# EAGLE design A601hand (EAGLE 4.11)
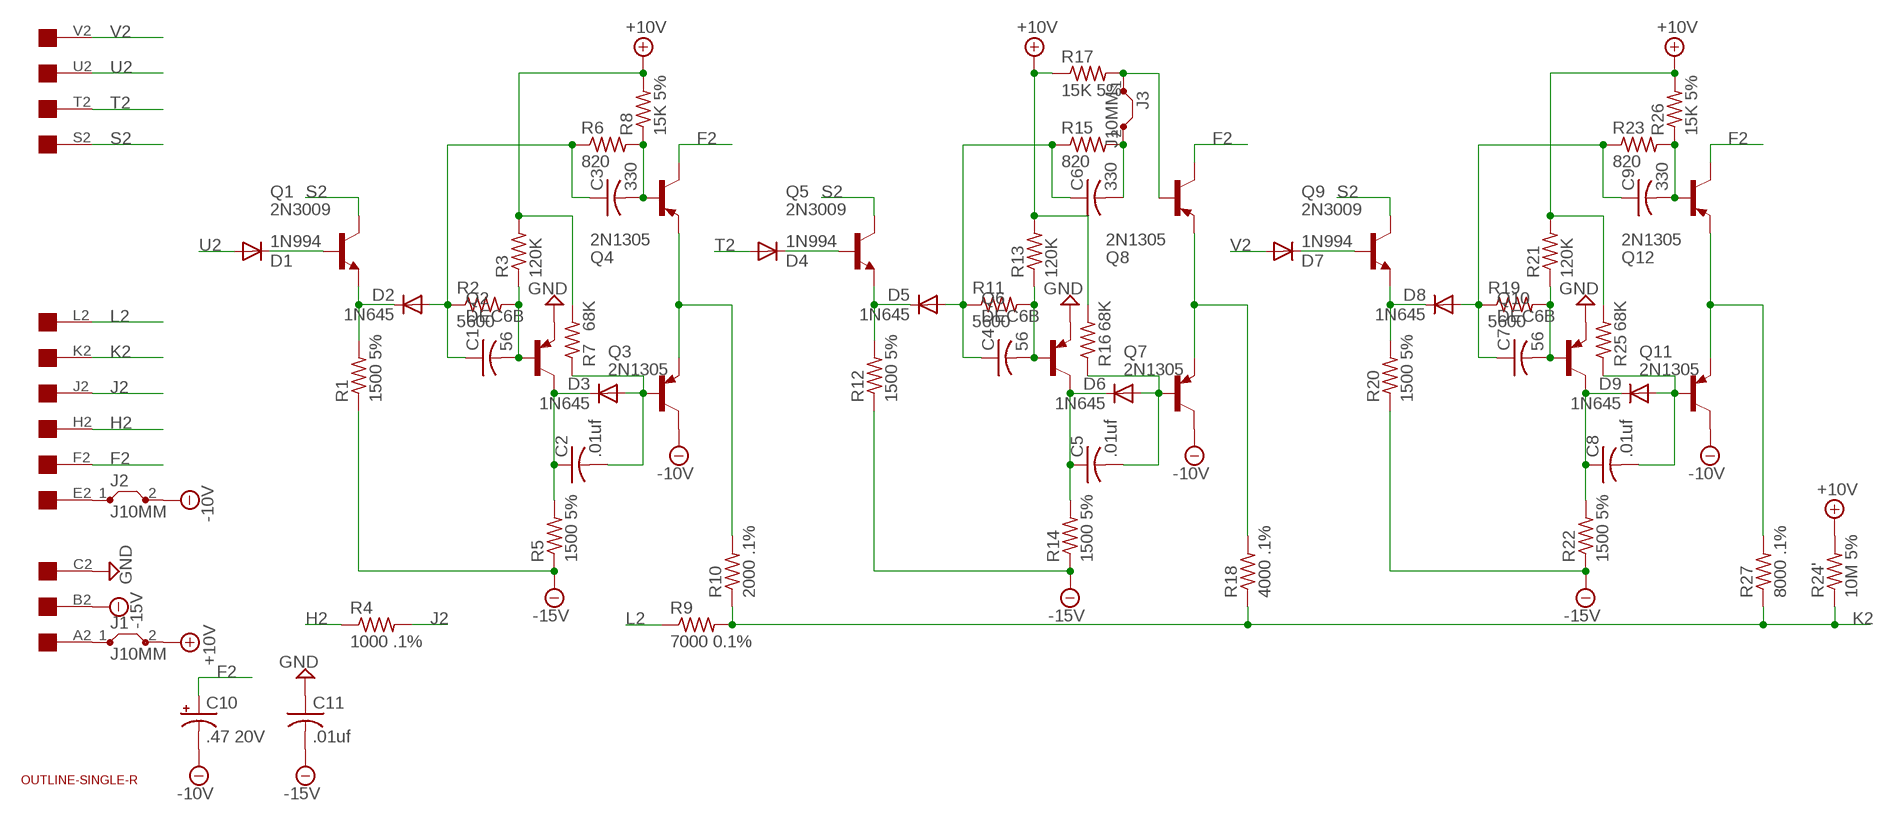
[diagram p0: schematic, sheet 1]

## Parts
C1  56  C-US075-032X103  [C075-032X103]
C2  .01uf  C-US050-025X075  [C050-025X075]
C3  330  C-US102-043X133  [C102-043X133]
C4  56  C-US075-032X103  [C075-032X103]
C5  .01uf  C-US050-025X075  [C050-025X075]
C6  330  C-US102-043X133  [C102-043X133]
C7  56  C-US075-032X103  [C075-032X103]
C8  .01uf  C-US050-025X075  [C050-025X075]
C9  330  C-US102-043X133  [C102-043X133]
C10  .47 20V  CPOL-USE22-6AXIAL  [E22-6]
C11  .01uf  C-US050-025X075  [C050-025X075]
D1  1N994  1N4148  [DO35-10]
D2  1N645  1N4148  [DO35-10]
D3  1N645  1N4148  [DO35-10]
D4  1N994  1N4148  [DO35-10]
D5  1N645  1N4148  [DO35-10]
D6  1N645  1N4148  [DO35-10]
D7  1N994  1N4148  [DO35-10]
D8  1N645  1N4148  [DO35-10]
D9  1N645  1N4148  [DO35-10]
J1  J10MM  [10]
J2  J10MM  [10]
J3  J10MM  [10]
Q1  2N3009  2N1613-NPN-TO39-EBC  [TO39]
Q2  DEC6B  2N2904A  [TO39]
Q3  2N1305  2N2904A  [TO39]
Q4  2N1305  2N2904A  [TO39]
Q5  2N3009  2N1613-NPN-TO39-EBC  [TO39]
Q6  DEC6B  2N2904A  [TO39]
Q7  2N1305  2N2904A  [TO39]
Q8  2N1305  2N2904A  [TO39]
Q9  2N3009  2N1613-NPN-TO39-EBC  [TO39]
Q10  DEC6B  2N2904A  [TO39]
Q11  2N1305  2N2904A  [TO39]
Q12  2N1305  2N2904A  [TO39]
R1  1500 5%  R-US_0207/10  [0207/10]
R2  5600  R-US_0207/10  [0207/10]
R3  120K  R-US_0207/10  [0207/10]
R4  1000 .1%  R-US_0309/12  [0309/12]
R5  1500 5%  R-US_0207/10  [0207/10]
R6  820  R-US_0207/10  [0207/10]
R7  68K  R-US_0207/10  [0207/10]
R8  15K 5%  R-US_0207/10  [0207/10]
R9  7000 0.1%  R-US_0309/12  [0309/12]
R10  2000 .1%  R-US_0309/12  [0309/12]
R11  5600  R-US_0207/10  [0207/10]
R12  1500 5%  R-US_0207/10  [0207/10]
R13  120K  R-US_0207/10  [0207/10]
R14  1500 5%  R-US_0207/10  [0207/10]
R15  820  R-US_0207/10  [0207/10]
R16  68K  R-US_0207/10  [0207/10]
R17  15K 5%  R-US_0207/10  [0207/10]
R18  4000 .1%  R-US_0309/12  [0309/12]
R19  5600  R-US_0207/10  [0207/10]
R20  1500 5%  R-US_0207/10  [0207/10]
R21  120K  R-US_0207/10  [0207/10]
R22  1500 5%  R-US_0207/10  [0207/10]
R23  820  R-US_0207/10  [0207/10]
R24'  10M 5%  R-US_0207/10  [0207/10]
R25  68K  R-US_0207/10  [0207/10]
R26  15K 5%  R-US_0207/10  [0207/10]
R27  8000 .1%  R-US_0309/12  [0309/12]
U$2  OUTLINE-SINGLE-R  [SINGLE-R]
U$3  EDGE-1  [EDGE-CON1]

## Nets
+10V: J1.2 R3.2 R7.2 R8.2 R13.2 R16.2 R17.1 R21.2 R24'.2 R25.2 R26.2
-10V: C10.- J2.2 Q3.3(C) Q7.3(C) Q11.3(C)
-15V: C11.2 R1.1 R5.1 R12.1 R14.1 R20.1 R22.1 U$3.B2
F2: C10.+ Q4.3(C) Q8.3(C) Q12.3(C) U$3.F2
GND [supply]: C11.1 Q2.1(E) Q6.1(E) Q10.1(E) U$3.C2
H2: R4.1 U$3.H2
J2: R4.2 U$3.J2
K2: R9.2 R10.1 R18.1 R24'.1 R27.1 U$3.K2
L2: R9.1 U$3.L2
N$1: D1.C Q1.2(B)
N$2: D2.C Q1.1(E) R1.2
N$3: C1.1 C3.1 D2.A R2.1 R6.1
N$4: C1.2 Q2.2(B) R2.2 R3.1
N$5: C3.2 Q4.2(B) R6.2 R8.1
N$6: C2.1 D3.C Q2.3(C) R5.2
N$7: C2.2 D3.A Q3.2(B) R7.1
N$8: Q3.1(E) Q4.1(E) R10.2
N$9: J2.1 U$3.E2
N$10: D4.C Q5.2(B)
N$11: D5.C Q5.1(E) R12.2
N$12: C4.1 C6.1 D5.A R11.1 R15.1
N$13: C4.2 Q6.2(B) R11.2 R13.1
N$14: C6.2 J3.2 R15.2
N$15: C5.1 D6.C Q6.3(C) R14.2
N$16: C5.2 D6.A Q7.2(B) R16.1
N$17: Q7.1(E) Q8.1(E) R18.2
N$18: D7.C Q9.2(B)
N$19: D8.C Q9.1(E) R20.2
N$20: C7.1 C9.1 D8.A R19.1 R23.1
N$21: C7.2 Q10.2(B) R19.2 R21.1
N$22: C9.2 Q12.2(B) R23.2 R26.1
N$23: C8.1 D9.C Q10.3(C) R22.2
N$24: C8.2 D9.A Q11.2(B) R25.1
N$25: Q11.1(E) Q12.1(E) R27.2
N$26: J1.1 U$3.A2
N$27: J3.1 Q8.2(B) R17.2
S2: Q1.3(C) Q5.3(C) Q9.3(C) U$3.S2
T2: D4.A U$3.T2
U2: D1.A U$3.U2
V2: D7.A U$3.V2
Unconnected: U$3.D2 U$3.M2 U$3.N2 U$3.P2 U$3.R2

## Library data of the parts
C1-C9 C11 = rcl:C-US: CAPACITOR, American symbol
C10 = rcl:CPOL-US: POLARIZED CAPACITOR, American symbol
D1-D9 = diode:1N4148: DIODE
J1-J3 = jumper:J: Bridge
Q1 Q5 Q9 = transistor:*-NPN-: NPN Transistror
Q2-Q4 Q6-Q8 Q10-Q12 = transistor-pnp:2N2904*: PNP Transistror
R1-R23 R24' R25-R27 = rcl:R-US_: RESISTOR, American symbol
U$2 = dec-con:OUTLINE-*: Board outlines for DEC boards.
U$3 = dec-con:EDGE-1: Single-Sided DEC Edge Connector -- (side 2)

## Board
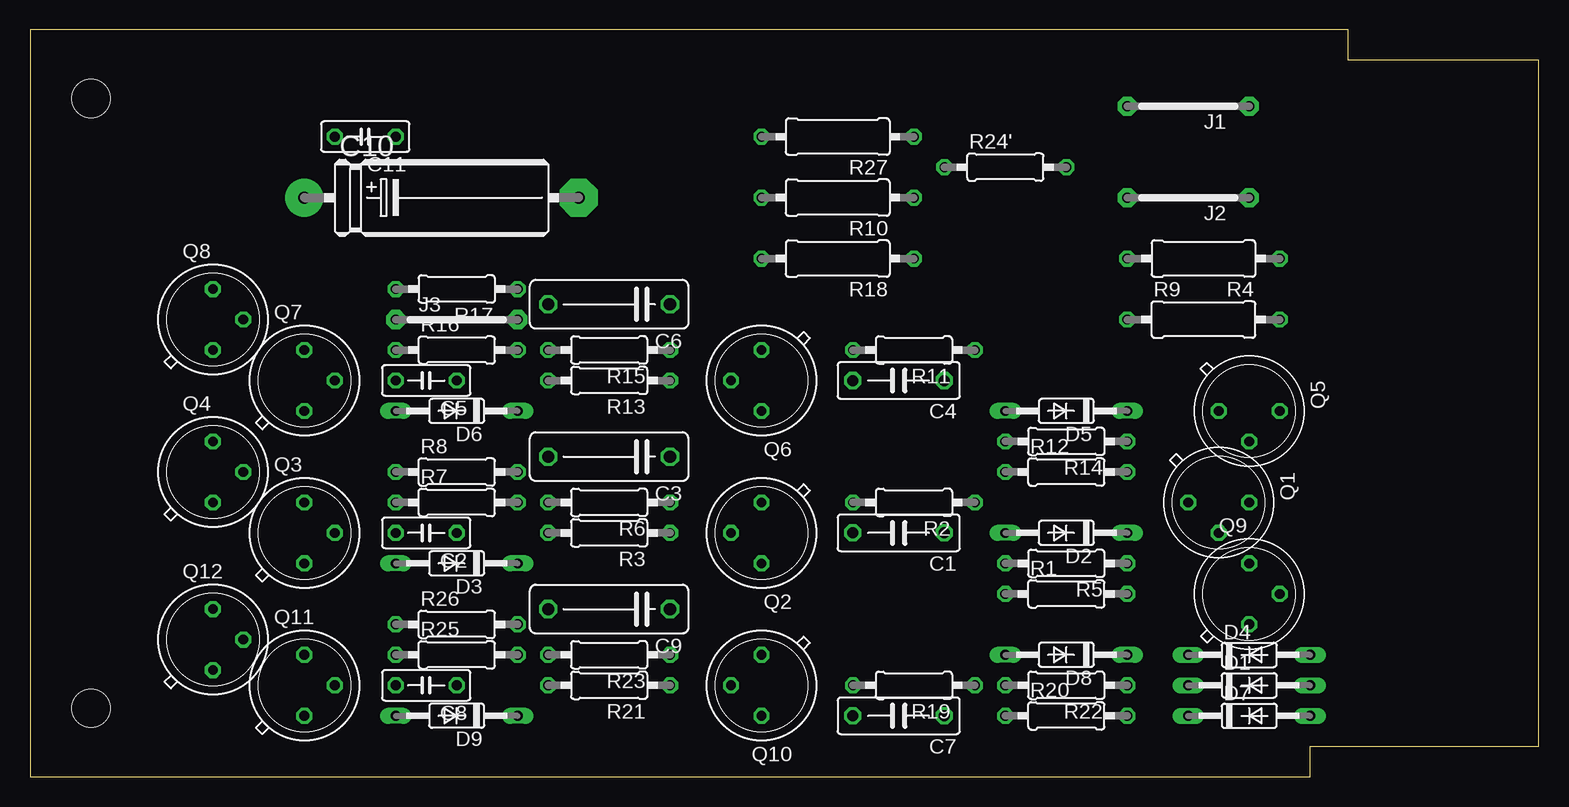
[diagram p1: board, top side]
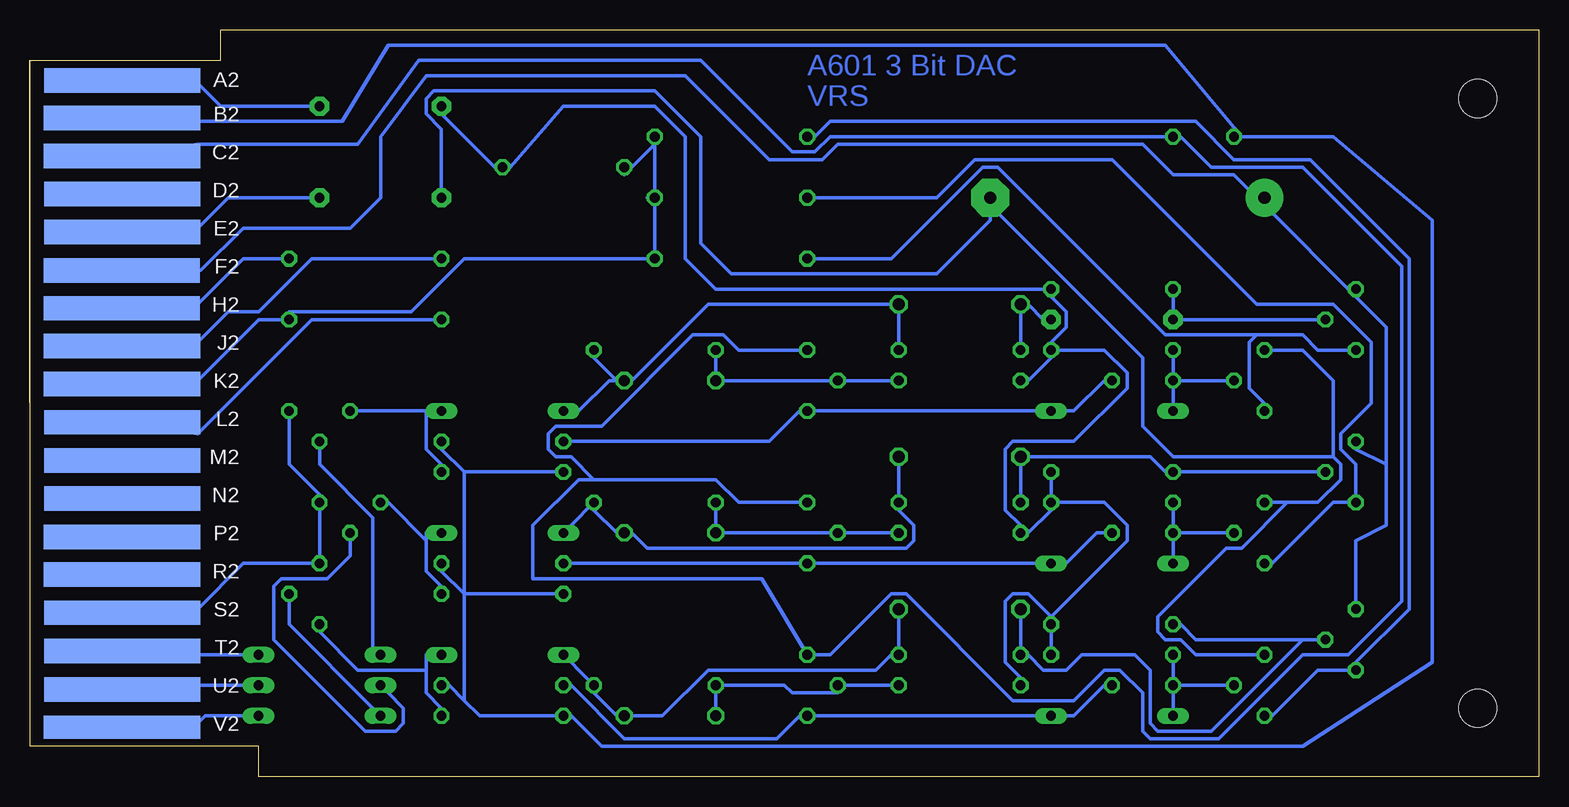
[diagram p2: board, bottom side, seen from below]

Size 125.73 x 62.23 mm. Coordinates in mm from the lower left corner, seen from the top.
Copper layers (1*16): Top 0.035mm / dielectric 1.5mm / Bottom 0.035mm
Design rules "15mils": minimum track width 12mil, minimum drill 24mil, track to track 12mil, track to pad 10mil, pad to pad 10mil, via to via 10mil, smd to smd 10mil, copper to edge 25mil, drill to drill 10mil, minimum pad ring 10mil, minimum via ring 8mil, stop-mask expansion 0mil, vias tented up to drill 0mil, thermal gap 10mil

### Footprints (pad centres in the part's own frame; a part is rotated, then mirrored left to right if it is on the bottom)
C075-032X103 = drill 0.914 octagon: 1 -3.81,0; 2 3.81,0
C050-025X075 = drill 0.813 octagon: 1 -2.54,0; 2 2.54,0
C102-043X133 = drill 1.016 octagon: 1 -5.08,0; 2 5.08,0
E22-6 = drill 1.016 pad 3.15 round: + -11.43,0 | drill 1.016 pad 3.15 octagon: - 11.43,0
DO35-10 = drill 0.813 long: A 5.08,0; C -5.08,0
10 = drill 0.813 pad 1.6 octagon: 1 -5.08,0; 2 5.08,0
TO39 = drill 0.813 octagon: 1 0,-2.54; 2 2.54,0; 3 0,2.54
0207/10 = drill 0.813 octagon: 1 -5.08,0; 2 5.08,0
0309/12 = drill 0.813 octagon: 1 -6.35,0; 2 6.35,0
SINGLE-R = hole 3.175: 5.08,5.715; 5.08,56.515
EDGE-CON1 = smd 13.017 x 2.032 bottom: A2 7.69,4.194; B2 7.668,7.328; C2 7.668,10.49; D2 7.693,13.665; E2 7.693,16.84; F2 7.642,20.041; H2 7.642,23.19; J2 7.668,26.34; K2 7.668,29.515; L2 7.693,32.69; M2 7.693,35.89; N2 7.693,39.04; P2 7.668,42.24; R2 7.668,45.39; S2 7.693,48.565; T2 7.693,51.74; U2 7.693,54.966 | smd 13.017 x 1.905 bottom: V2 7.668,58.102

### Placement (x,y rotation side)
C1  72.39,20.32 180 top
C2  33.02,20.32 180 top
C3  48.26,26.67 180 top
C4  72.39,33.02 180 top
C5  33.02,33.02 180 top
C6  48.26,39.37 180 top
C7  72.39,5.08 180 top
C8  33.02,7.62 180 top
C9  48.26,13.97 180 top
C10  34.29,48.26 0 top
C11  27.94,53.34 180 top
D1  101.6,7.62 0 top
D2  86.36,20.32 180 top
D3  35.56,17.78 180 top
D4  101.6,10.16 0 top
D5  86.36,30.48 180 top
D6  35.56,30.48 180 top
D7  101.6,5.08 0 top
D8  86.36,10.16 180 top
D9  35.56,5.08 180 top
J1  96.52,55.88 180 top
J2  96.52,48.26 180 top
J3  35.56,38.1 0 top
Q1  99.06,22.86 270 top
Q2  60.96,20.32 180 top
Q3  22.86,20.32 0 top
Q4  15.24,25.4 0 top
Q5  101.6,30.48 270 top
Q6  60.96,33.02 180 top
Q7  22.86,33.02 0 top
Q8  15.24,38.1 0 top
Q9  101.6,15.24 0 top
Q10  60.96,7.62 180 top
Q11  22.86,7.62 0 top
Q12  15.24,11.43 0 top
R1  86.36,15.24 0 top
R2  73.66,22.86 180 top
R3  48.26,20.32 180 top
R4  97.79,43.18 180 top
R5  86.36,17.78 180 top
R6  48.26,22.86 180 top
R7  35.56,22.86 0 top
R8  35.56,25.4 0 top
R9  97.79,38.1 0 top
R10  67.31,48.26 180 top
R11  73.66,35.56 180 top
R12  86.36,25.4 0 top
R13  48.26,33.02 180 top
R14  86.36,27.94 180 top
R15  48.26,35.56 180 top
R16  35.56,35.56 0 top
R17  35.56,40.64 180 top
R18  67.31,43.18 180 top
R19  73.66,7.62 180 top
R20  86.36,5.08 0 top
R21  48.26,7.62 180 top
R22  86.36,7.62 180 top
R23  48.26,10.16 180 top
R24'  81.28,50.8 0 top
R25  35.56,10.16 0 top
R26  35.56,12.7 0 top
R27  67.31,53.34 180 top
U$2  0,0 0 top
U$3  125.73,62.23 180 top

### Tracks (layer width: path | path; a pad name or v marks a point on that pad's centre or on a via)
+10V
  Bottom 0.305: R25.2 40.64,10.79 40.64,12.06 R26.2 | 40.64,13.34 42.55,15.24 43.81,15.24 44.45,14.61 44.45,9.53 43.18,8.26 R21.2 | R26.2 40.64,13.34 | R7.2 40.64,23.5 40.64,24.77 R8.2 | R7.2 40.64,22.23 42.55,20.32 R3.2 43.18,20.95 44.45,22.23 44.45,27.3 43.81,27.94 38.73,27.94 34.29,32.38 34.29,33.66 36.2,35.56 40.01,35.56 R16.2 | R13.2 42.55,33.02 40.64,34.92 R16.2 | R16.2 40.64,36.2 39.37,37.47 39.37,38.73 40.64,40.01 R17.1 41.27,40.64 55.24,40.64 55.88,40.64 68.58,40.64 71.12,43.18 71.12,53.34 73.66,55.88 81.28,55.88 85.72,50.8 R24'.2 87,50.8 91.44,55.24 J1.2 | 40.64,13.34 34.29,19.68 34.29,20.95 36.2,22.86 40.01,22.86 R7.2 | R26.2 40.64,13.34
-10V
  Bottom 0.305: 17.14,26.67 30.48,26.67 33.02,29.21 33.02,34.92 45.09,46.99 C10.- 45.72,46.35 50.16,41.91 67.31,41.91 69.85,44.45 69.85,53.34 73.66,57.15 92.08,57.15 92.71,56.52 92.71,55.24 91.44,53.98 91.44,48.9 J2.2 | 17.14,26.67 16.51,26.04 16.51,24.77 18.41,22.86 20.95,22.86 | 20.95,22.86 22.23,22.86 Q3.3 | 20.95,22.86 24.77,19.05 26.04,19.05 31.75,13.34 31.75,12.06 31.11,11.43 29.84,11.43 28.57,10.16 23.5,10.16 Q11.3 | 17.14,26.67 17.14,33.02 19.68,35.56 Q7.3
-15V
  Bottom 0.305: R1.1 81.92,15.24 89.53,15.24 | 89.53,6.35 90.81,7.62 R22.1 | 89.53,6.35 88.27,5.08 81.92,5.08 R20.1 80.64,5.08 78.11,2.54 19.68,2.54 8.89,9.53 8.89,46.35 17.14,53.34 24.77,53.34 | 89.53,15.24 91.44,17.14 R5.1 | 89.53,6.35 89.53,15.24 | 89.53,25.4 91.44,27.3 R14.1 | 89.53,15.24 89.53,25.4 | 24.77,53.34 C11.2 | 24.77,53.34 31.11,60.96 95.89,60.96 99.69,54.61 111.76,54.61 U$3.B2 | 24.77,53.34 C11.2 | 89.53,25.4 81.92,25.4 R12.1 | 24.77,53.34 C11.2
F2
  Bottom 0.305: 12.7,26.04 12.7,20.95 15.24,19.68 15.24,14.61 Q12.3 | 12.7,26.04 15.24,27.3 Q4.3 | 12.7,26.04 12.7,37.47 15.24,40.01 Q8.3 15.88,40.64 22.23,46.99 C10.+ | U$3.F2 111.48,42.19 107.95,45.72 104.14,45.72 99.06,45.72 96.52,48.26 96.52,53.34 92.71,58.42 71.12,58.42 64.14,51.44 59.69,51.44 58.42,52.7 33.02,52.7 30.48,50.16 25.4,50.16 24.13,48.9 | C10.+ 24.13,48.9 | C10.+ 24.13,48.9
GND
  Bottom 0.305: U$3.C2 111.76,52.7 98.42,52.7 93.34,59.69 69.85,59.69 62.23,52.07 60.33,52.07 59.05,53.34 52.7,53.34 31.11,53.34 C11.1 29.84,53.34 27.3,50.8 19.68,50.8 11.43,42.55 11.43,14.61 15.88,10.16 19.68,10.16 26.67,3.17 32.38,3.17 33.02,3.81 33.02,6.99 34.92,8.89 36.2,8.89 38.73,6.35 43.81,6.35 52.7,15.24 53.98,15.24 59.05,10.16 60.33,10.16 Q10.1 64.77,16.51 83.82,16.51 83.82,20.95 80.01,24.77 78.74,24.77 | 78.74,24.77 68.58,24.77 66.67,22.86 61.59,22.86 Q2.1 | 78.74,24.77 80.64,26.67 81.92,26.67 82.55,27.3 82.55,28.57 81.92,29.21 78.11,29.21 70.48,36.83 67.94,36.83 66.67,35.56 61.59,35.56 Q6.1
H2
  Bottom 0.305: R4.1 104.78,43.18 107.95,43.18 111.76,39.37 U$3.H2
J2
  Bottom 0.305: R4.2 92.08,43.18 102.23,43.18 106.68,38.73 109.22,38.73 111.76,36.2 U$3.J2
K2
  Bottom 0.305: 73.66,43.81 73.66,47.62 R10.1 74.3,48.26 | 73.66,43.81 73.66,52.7 | 73.66,52.7 R27.1 73.66,52.7 | 76.2,50.16 R24'.1 75.56,50.8 73.66,52.7 | U$3.K2 111.76,33.02 106.68,38.1 104.78,38.1 R9.2 104.14,38.73 93.98,38.73 89.53,43.18 74.3,43.18 R18.1 73.66,43.81
L2
  Bottom 0.305: R9.1 92.08,38.1 102.23,38.1 111.76,28.57 U$3.L2
N$1
  Bottom 0.305: D1.C 95.89,6.99 94.61,5.71 94.61,4.45 95.25,3.81 97.79,3.81 105.41,11.43 105.41,15.88 104.78,16.51 100.97,16.51 99.06,18.41 99.06,19.68 Q1.2
N$2
  Bottom 0.305: 92.71,19.68 92.71,20.32 D2.C | 92.71,19.68 92.71,17.14 91.44,15.88 R1.2 | 92.71,19.68 95.89,22.86 Q1.1
N$3
  Bottom 0.305: C3.1 53.34,26.04 53.34,23.5 R6.1 53.34,22.23 52.07,20.95 52.07,19.68 52.7,19.05 74.3,19.05 75.56,20.32 C1.1 76.83,20.32 78.74,22.23 R2.1 80.64,20.95 D2.A
N$4
  Bottom 0.305: R2.2 68.58,22.23 68.58,20.95 C1.2 67.94,20.32 59.05,20.32 Q2.2 57.78,20.32 53.98,20.32 R3.1
N$5
  Bottom 0.305: R6.2 43.18,23.5 43.18,26.04 C3.2 42.55,26.67 32.38,26.67 31.11,25.4 R8.1 29.84,25.4 18.41,25.4 Q4.2
N$6
  Bottom 0.305: C2.1 36.2,20.32 36.83,20.32 39.37,17.78 D3.C 41.91,17.78 60.33,17.78 Q2.3 61.59,17.78 80.64,17.78 R5.2
N$7
  Bottom 0.305: Q3.2 26.04,20.32 29.84,20.32 C2.2 | D3.A 30.48,18.41 30.48,19.68 C2.2 | R7.1 30.48,22.23 30.48,20.95 C2.2
N$8
  Bottom 0.305: Q3.1 22.23,17.78 17.14,22.86 15.88,22.86 Q4.1 15.24,23.5 15.24,26.04 16.51,27.3 16.51,28.57 13.97,31.11 13.97,36.2 17.14,39.37 23.5,39.37 35.56,51.44 46.99,51.44 50.16,48.26 60.33,48.26 R10.2
N$9
  Bottom 0.305: J2.1 102.23,48.26 109.22,48.26 111.76,45.72 U$3.E2
N$10
  Bottom 0.305: D4.C 97.16,10.79 97.16,21.59 101.6,26.04 101.6,27.3 Q5.2
N$11
  Bottom 0.305: 92.71,30.48 92.71,27.3 91.44,26.04 R12.2 | 92.71,30.48 D5.C 92.71,30.48 | 92.71,30.48 98.42,30.48 Q5.1
N$12
  Bottom 0.305: R15.1 53.34,36.2 53.34,38.73 C6.1 53.98,39.37 69.22,39.37 75.56,33.02 C4.1 | 76.83,33.02 77.47,33.02 80.01,30.48 D5.A | C4.1 76.83,33.02 | 76.83,33.02 78.74,34.92 R11.1 | C4.1 76.83,33.02
N$13
  Bottom 0.305: R11.2 68.58,34.92 68.58,33.66 C4.2 67.94,33.02 59.05,33.02 Q6.2 57.78,33.02 53.98,33.02 R13.1
N$14
  Bottom 0.305: R15.2 43.18,36.2 43.18,38.73 C6.2 42.55,39.37 41.27,38.1 J3.2
N$15
  Bottom 0.305: C5.1 36.2,33.02 38.73,30.48 39.37,30.48 D6.C 41.91,30.48 60.33,30.48 Q6.3 61.59,30.48 64.14,27.94 80.64,27.94 R14.2
N$16
  Bottom 0.305: Q7.2 26.04,33.02 29.84,33.02 C5.2 | D6.A 30.48,31.11 30.48,32.38 C5.2 | R16.1 30.48,34.92 30.48,33.66 C5.2
N$17
  Bottom 0.305: 23.5,36.83 19.68,36.83 18.41,35.56 15.88,35.56 Q8.1 | 23.5,36.83 24.13,36.2 24.13,32.38 22.86,31.11 Q7.1 | 23.5,36.83 31.11,36.83 45.09,50.8 46.35,50.8 53.98,43.18 57.78,43.18 60.33,43.18 R18.2
N$18
  Bottom 0.305: D7.C 97.16,5.71 104.14,12.7 104.14,14.61 Q9.2
N$19
  Bottom 0.305: 92.71,8.89 92.71,10.16 D8.C | 92.71,8.89 92.71,6.99 91.44,5.71 R20.2 | 92.71,8.89 98.42,8.89 101.6,12.06 Q9.1
N$20
  Bottom 0.305: D8.A 80.64,9.53 80.01,8.89 R19.1 78.74,6.99 76.83,5.08 C7.1 75.56,5.08 73.03,5.08 69.22,8.89 55.24,8.89 53.98,10.16 R23.1 53.34,10.79 53.34,13.34 C9.1
N$21
  Bottom 0.305: C7.2 68.58,5.71 68.58,6.99 R19.2 67.94,7.62 62.87,7.62 62.23,6.99 58.42,6.99 Q10.2 57.78,7.62 53.98,7.62 R21.1
N$22
  Bottom 0.305: C9.2 43.18,13.34 43.18,10.79 R23.2 42.55,10.16 41.27,8.89 39.37,8.89 38.1,10.16 33.66,10.16 32.38,8.89 32.38,4.45 31.75,3.81 27.3,3.81 19.68,11.43 | 19.68,11.43 28.57,11.43 29.84,12.7 R26.1 | 19.68,11.43 18.41,11.43 Q12.2
N$23
  Bottom 0.305: C8.1 36.2,7.62 38.73,5.08 39.37,5.08 D9.C 41.91,5.08 60.33,5.08 Q10.3 61.59,5.08 63.5,3.17 76.2,3.17 80.64,7.62 R22.2
N$24
  Bottom 0.305: Q11.2 26.04,7.62 29.84,7.62 C8.2 | D9.A 30.48,5.71 30.48,6.99 C8.2 | R25.1 30.48,9.53 30.48,8.26 C8.2
N$25
  Bottom 0.305: Q11.1 22.23,5.08 18.41,8.89 15.88,8.89 Q12.1 15.24,9.53 10.79,13.97 10.79,43.18 19.05,51.44 25.4,51.44 28.57,54.61 59.05,54.61 60.33,53.34 R27.2
N$26
  Bottom 0.305: J1.1 102.23,55.88 109.86,55.88 111.76,57.78 U$3.A2
N$27
  Bottom 0.305: Q8.2 18.41,38.1 29.84,38.1 J3.1 30.48,38.73 30.48,40.01 R17.2
S2
  Bottom 0.305: Q5.3 104.14,29.84 104.14,26.04 101.6,23.5 Q1.3 101.6,22.23 101.6,18.41 Q9.3 102.23,17.78 107.95,17.78 111.76,13.97 U$3.S2
T2
  Bottom 0.305: D4.A 107.95,10.16 111.76,10.16 U$3.T2
U2
  Bottom 0.305: D1.A 107.95,7.62 111.76,7.62 U$3.U2
V2
  Bottom 0.305: D7.A 107.95,5.08 111.12,5.08 111.76,4.45 U$3.V2

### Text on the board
Bottom: A601 3 Bit DAC | VRS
